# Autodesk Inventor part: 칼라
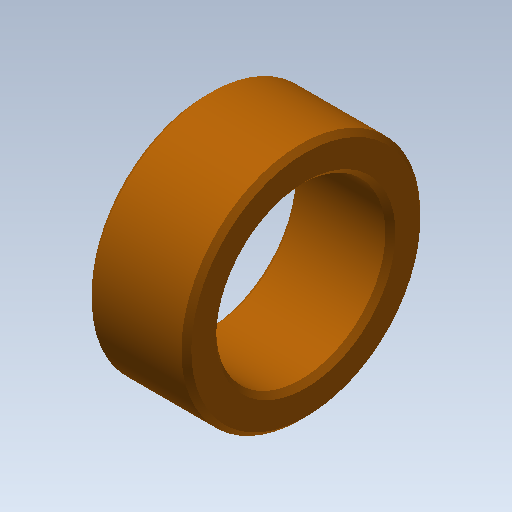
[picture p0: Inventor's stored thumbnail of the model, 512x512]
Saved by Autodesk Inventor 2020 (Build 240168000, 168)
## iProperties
Created: 2015-09
Part Number: 칼라
Material: 강철, 연강
Document SubType Name: Modeling
Designer: mduedu
Density: 7.86 g/cm^3
Description: 외주 가공
Mass: 17.8983 g
Surface Area: 15.6581 cm^2
Volume: 2.27713 cm^3
Appearance: 주황색
Author: mduedu
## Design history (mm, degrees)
sketch "스케치1"
  geometry: C1 r 12 at (0, 0); C2 r 8.5 at (0, 0); 1 further point
  constraints: 2 centre point, 2 coincident
  dimensions: "d0" = 24 diameter of C1; "d2" = 17 diameter of C2
extrude "돌출1" new body sketch "스케치1" distance "d3" = 10; taper "d4" = 0 deg
chamfer "모따기1" distance "d5" = 0.5; stored, may be unused: second distance "d6" = 2, angle "d7" = 45 deg
node "솔리드1"
